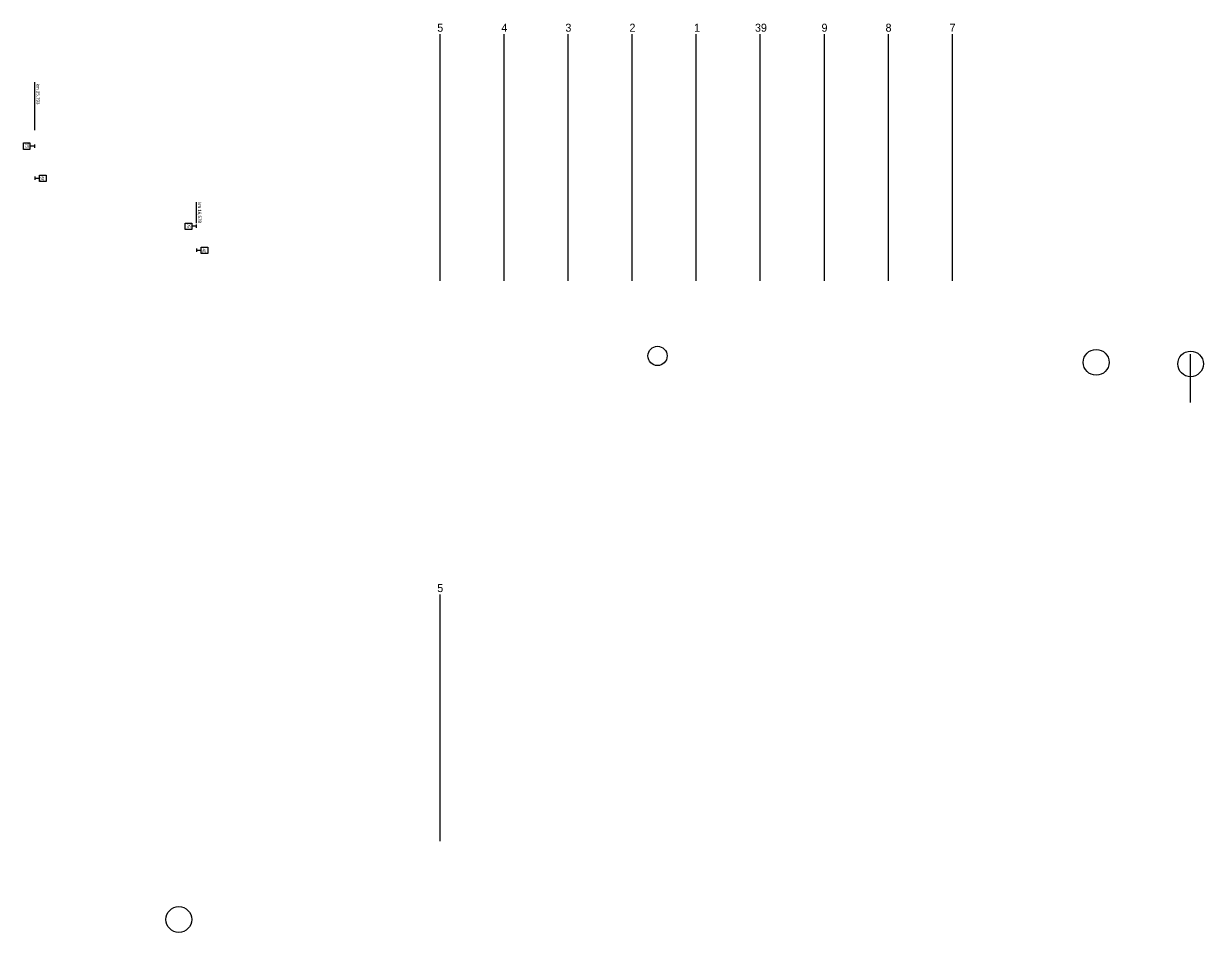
# Model space of a CAD drawing. Extents: x -630 to 5777, y 380 to 2087.
# Drawn here: x 5040 to 5777, y 1519 to 2087 of the extents above; entities that cross this region are included whole.
import ezdxf

# ---------------------------------------------------------------- set-up
doc = ezdxf.new("R2010")
doc.units = 0
doc.layers.add('rychlostník', color=7, linetype='Continuous')
doc.layers.add('Vrstva 1', color=7, linetype='Continuous')

msp = doc.modelspace()

# ---------------------------------------------------------------- linework, layer by layer
for p, q in [((5300, 2080), (5300, 1926)), ((5340, 2080), (5340, 1926)), ((5380, 2080), (5380, 1926)), ((5420, 2080), (5420, 1926)), ((5460, 2080), (5460, 1926)), ((5500, 2080), (5500, 1926)), ((5540, 2080), (5540, 1926)), ((5580, 2080), (5580, 1926)), ((5620, 2080), (5620, 1926)), ((5769, 1850), (5769, 1880)), ((5300, 1730), (5300, 1576))]:
    msp.add_line(p, q)
for centre, radius in [((5436, 1879), 6), ((5710, 1875), 8.06), ((5769, 1874), 8), ((5137, 1527), 8.06)]:
    msp.add_circle(centre, radius)
at = {"layer": 'rychlostník'}
for p, q in [((5047, 2020), (5047, 2050)), ((5047, 2020), (5047, 2050)), ((5040, 2008), (5040, 2012)), ((5040, 2012), (5044, 2012)), ((5044, 2008), (5040, 2008)), ((5042.33, 2010.09), (5042.33, 2010.09)), ((5044, 2012), (5044, 2008)), ((5047, 2010), (5044, 2010)), ((5047, 2009), (5047, 2011)), ((5047, 1991), (5047, 1989)), ((5047, 1990), (5050, 1990)), ((5050, 1992), (5054, 1992)), ((5050, 1988), (5050, 1992)), ((5051.67, 1989.91), (5051.67, 1989.91)), ((5054, 1992), (5054, 1988)), ((5054, 1988), (5050, 1988)), ((5148, 1962), (5148, 1975)), ((5141, 1958), (5141, 1962)), ((5141, 1962), (5145, 1962)), ((5145, 1962), (5145, 1958)), ((5148, 1959), (5148, 1961)), ((5145, 1958), (5141, 1958)), ((5143.33, 1960.09), (5143.33, 1960.09)), ((5148, 1960), (5145, 1960)), ((5148, 1946), (5148, 1944)), ((5151, 1947), (5155, 1947)), ((5151, 1943), (5151, 1947)), ((5155, 1947), (5155, 1943)), ((5148, 1945), (5151, 1945)), ((5155, 1943), (5151, 1943))]:
    msp.add_line(p, q, dxfattribs=at)

# ---------------------------------------------------------------- texts
for s, rotation, p in [('km 25,793', 270, (5048, 2049)), ('55', 90, (5043.33, 2008.93)), ('50', 270, (5050.67, 1991.07)), ('km 16,578', 270, (5149, 1975)), ('50', 90, (5144.33, 1958.93)), ('40', 270, (5151.67, 1946.07))]:
    msp.add_text(s, height=2, rotation=rotation, dxfattribs=at).set_placement(p)
at = {"layer": 'Vrstva 1'}
for s, p in [('5', (5298.43, 2081.5)), ('4', (5338.46, 2081.5)), ('3', (5378.45, 2081.5)), ('2', (5418.47, 2081.5)), ('1', (5458.84, 2081.5)), ('39', (5496.89, 2081.5)), ('9', (5538.45, 2081.5)), ('8', (5578.45, 2081.5)), ('7', (5618.45, 2081.5)), ('5', (5298.43, 1731.5))]:
    msp.add_text(s, height=5, dxfattribs=at).set_placement(p)

doc.saveas('drawing.dxf')
